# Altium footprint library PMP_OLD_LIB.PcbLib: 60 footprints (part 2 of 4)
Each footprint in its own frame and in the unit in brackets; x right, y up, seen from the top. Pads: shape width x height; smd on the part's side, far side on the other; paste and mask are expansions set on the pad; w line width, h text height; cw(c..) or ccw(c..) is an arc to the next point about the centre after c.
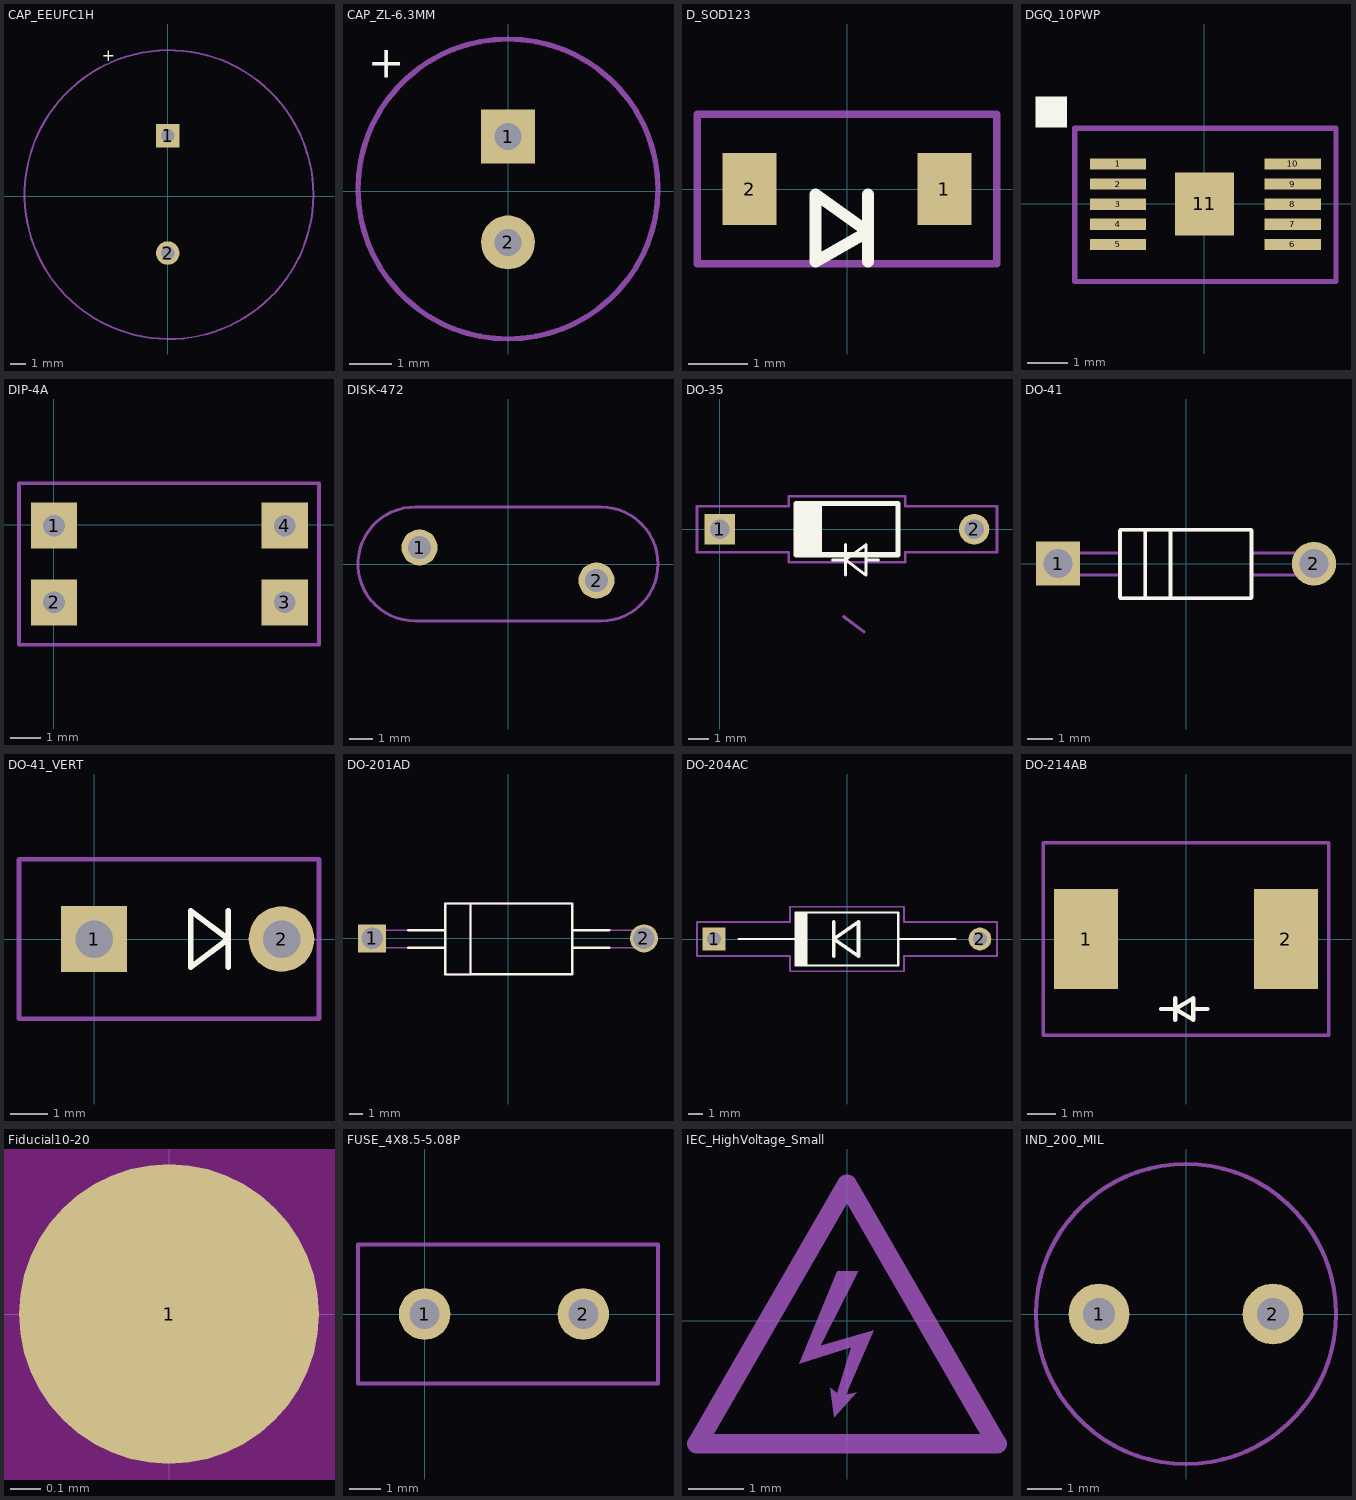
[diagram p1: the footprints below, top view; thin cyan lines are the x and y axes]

## CAP_EEUFC1H [mil]
pads (2):
  rect 60x60 hole 35: 1(0.1,155)
  round 60 hole 35: 2(0,-145)
Top Overlay:
  text "+" at -133.85,372.79 h30
Mechanical 5:
  circle w5: c3.4,4.6 r369.5
  text "+" at -145,380 h30
  text ".Designator" at -385,350 h60

## CAP_ZL-6.3MM [mil]
pads (2):
  rect 50x50 hole 25: 1(0,50.5)
  round 50 hole 25: 2(0,-47.5)
Top Overlay:
  text "+" at -130,105 h30
Mechanical 5:
  circle w5: c0,2 r139
  text "+" at -130,105 h30
  text ".Designator" at 135,-55 h60

## D_SOD123 [mil]
pads (2):
  rect 36x48 smd: 1(65,0) 2(-65,0)
Top Overlay:
  lines w8: 14,-48.5 14,-3.5 ; -21,-48.5 14,-28.5 -21,-3.5 -21,-48.5
Mechanical 5:
  lines w5: 14,-49.5 14,-4.5 ; -100,-50 100,-50 100,50 -100,50 -100,-50 ; -21,-49.5 14,-29.5 -21,-4.5 -21,-49.5
  text ".Designator" at -107,-110 h40

## DGQ_10PWP [mil]
pads (11):
  rect 55x11 smd: 1(-84.5,39) 2(-84.5,19.3) 3(-84.5,-0.4) 4(-84.5,-20.1) 5(-84.5,-39.8) 6(86.5,-39.8) 7(86.5,-20.1) 8(86.5,-0.4) 9(86.5,19.3) 10(86.5,39)
  rect 57.87x61.81 smd: 11(0,0)
Top Overlay:
  region: -165,75 -135,75 -135,105 -165,105
Mechanical 5:
  lines w5: -127,-76 128.9,-76 128.9,74 -127,74 -127,-76
  text "*" at -153.5,55.2 h60
  text ".Designator" at 27.5,-115.8 h60

## DIP-4A [mil]
pads (4):
  rect 60x60 hole 28: 1(0.5,-1) 2(0.5,-101) 3(300.5,-101) 4(300.5,-1)
Mechanical 5:
  lines w5: -45,-156 -45,54 345,54 345,-156 -45,-156
  text ".Designator" at -65,-90 h60

## DISK-472 [mil]
pads (2):
  round 60 hole 38: 1(-147.5,27.5) 2(147.5,-27.5)
Mechanical 5:
  lines w5: -154.17,95 ccw(c-155,0) -155,-95 155,-95 ccw(c155,0) 155,95 -154.1,95
  text ".Designator" at 295,-35 h60

## DO-35 [mil]
pads (2):
  rect 60x60 hole 38: 1(0,0)
  round 60 hole 38: 2(500,0)
Top Overlay:
  region: 150,-50 200,-50 200,50 150,50
  lines w6: 247,-60 287,-90 ; 247,-60 287,-30 ; 247,-60 287,-30 ; 247,-60 287,-90 ; 247,-60 222,-60 247,-60 ; 287,-90 287,-30 ; 287,-90 287,-30 ; 247,-90 247,-30 247,-90 ; 287,-60 312,-60 287,-60
  lines w10: 150,50 150,-50 350,-50 350,50 ; 150,51 350,51
Mechanical 5:
  lines w5: -45,-45 135,-45 135,-65 365,-65 365,-45 545,-45 545,45 365,45 365,65 135,65 135,45 -45,45 -45,-45
  lines w6: 243,-171.5 283,-201.5
  text ".Designator" at 198,93.5 h60

## DO-41 [mm] "diode"
height 3
pads (2):
  rect 1.75x1.75 hole 1.15: 1(-5.08,0)
  round 1.75 hole 1.15: 2(5.08,0)
Top Overlay:
  lines w0.152: -1.615,-1.371 -0.615,-1.371 ; -1.615,1.347 -0.615,1.347 ; -2.615,-1.322 ccw(c-2.565,-1.322) -2.565,-1.372 -1.615,-1.372 -1.615,-0.012 -1.615,1.348 -2.565,1.348 ccw(c-2.565,1.298) -2.615,1.298 -2.615,-0.012 -2.615,-1.322 ; -0.615,-1.372 -0.615,1.348 2.545,1.348 cw(c2.545,1.298) 2.595,1.298 2.595,-1.322 cw(c2.545,-1.322) 2.545,-1.372 -0.615,-1.372
Mechanical 5:
  lines w0.127: -2.615,-0.444 -4.09,-0.444 -5.09,-0.444 cw(c-5.09,-0.012) -5.522,-0.012 cw(c-5.09,-0.012) -5.09,0.42 -4.09,0.42 -2.615,0.42 ; -1.615,-1.371 -0.615,-1.371 ; -1.615,1.347 -0.615,1.347 ; 2.595,-0.444 4.07,-0.444 5.07,-0.444 ccw(c5.07,-0.012) 5.502,-0.012 ccw(c5.07,-0.012) 5.07,0.42 4.07,0.42 2.595,0.42 ; -2.615,-1.322 ccw(c-2.565,-1.322) -2.565,-1.372 -1.615,-1.372 -1.615,-0.012 -1.615,1.348 -2.565,1.348 ccw(c-2.565,1.298) -2.615,1.298 -2.615,-0.012 -2.615,-1.322 ; -0.615,-1.372 2.545,-1.372 ccw(c2.545,-1.322) 2.595,-1.322 2.595,1.298 ccw(c2.545,1.298) 2.545,1.348 -0.615,1.348 -0.615,-1.372
  text ".Designator" at -1.905,2.54 h1.52
3D body: height 2.72, standoff -2.6, extent -5.512,-1.36 5.512,1.36

## DO-41_VERT [mil]
pads (2):
  rect 70x70 hole 40: 1(0,0)
  round 70 hole 40: 2(200,0)
Top Overlay:
  lines w6: 103,-30 143,0 ; 103,-30 143,0 ; 103,-30 103,30 ; 103,-30 103,30 ; 103,30 143,0 ; 103,30 143,0 ; 143,-30 143,30 143,-30
Mechanical 5:
  lines w5: 103,-30 143,0 ; 103,-30 103,30 ; 103,-30 103,30 ; 103,-30 143,0 ; 103,30 143,0 ; 103,30 143,0 ; -80,-85 -80,85 240,85 240,-85 -80,-85 ; 143,-30 143,30 143,-30
  text ".Designator" at 25,110 h60

## DO-201AD [mm] "Vishay dimensions"
height 5.5
pads (2):
  rect 2.1x2.1 hole 1.6: 1(-10.16,0)
  round 2.1 hole 1.6: 2(10.16,0)
Top Overlay:
  lines w0.178: -7.47,-0.7 -4.7,-0.7 ; -7.47,0.62 -4.7,0.62 ; -2.8,-2.69 4.8,-2.69 4.8,2.61 -2.8,2.61 ; 4.8,-0.7 7.57,-0.7 ; 4.8,0.62 7.57,0.62 ; -2.8,2.61 -4.7,2.61 -4.7,-2.7 -2.8,-2.7 -2.8,2.61
Mechanical 5:
  lines w0.127: -4.7,-0.7 -7.47,-0.7 -10.11,-0.7 cw(c-10.11,-0.04) -10.11,0.62 -7.47,0.62 -4.7,0.62 ; -2.8,-2.69 4.8,-2.69 4.8,2.61 -2.8,2.61 ; 4.8,-0.7 7.57,-0.7 10.21,-0.7 ccw(c10.21,-0.04) 10.21,0.62 7.57,0.62 4.8,0.62 ; -2.8,2.61 -2.8,-2.7 -4.7,-2.7 -4.7,2.61 -2.8,2.61
  text ".Designator" at -0.864,3.81 h1.52
3D body: height 5.3, standoff -2.54, extent -10.819,-2.68 10.819,2.609

## DO-204AC [mil]
pads (2):
  rect 60x60 hole 37: 1(-350,0)
  round 60 hole 37: 2(350,0)
Top Overlay:
  region: -135,-70 -105,-70 -105,70 -135,70
  lines w6: -285,0 -135,0 ; 135,0 285,0 ; -135,-70 -135,70 135,70 135,-70 -135,-70
  lines w10: -35,-45 -35,45 ; -35,0 30,-45 30,45 -35,0
Mechanical 5:
  lines w5: -395,-45 -395,45 -150,45 -150,85 150,85 150,45 395,45 395,-45 150,-45 150,-85 -150,-85 -150,-45 -395,-45
  text ".Designator" at 370,-85 h60

## DO-214AB [mil]
pads (2):
  rect 90x140 smd: 1(-140,0) 2(140,0)
Top Overlay:
  lines w6: -15,-98 -35,-98 -15,-98 ; -15,-98 10,-113 ; -15,-98 10,-83 ; -15,-98 10,-113 ; -15,-98 10,-83 ; 10,-113 10,-83 ; 10,-113 10,-83 ; -15,-113 -15,-83 -15,-113 ; 10,-98 30,-98 10,-98
Mechanical 5:
  lines w5: -15,-98 -35,-98 -15,-98 ; -15,-98 10,-83 ; -15,-98 10,-113 ; -15,-98 10,-83 ; -15,-98 10,-113 ; 10,-113 10,-83 ; 10,-113 10,-83 ; -200,-135 -200,135 200,135 200,-135 -200,-135 ; -15,-113 -15,-83 -15,-113 ; 10,-98 30,-98 10,-98
  text ".Designator" at -55,-225 h60

## Fiducial10-20 [mm]
pads (1):
  round 1 smd paste+0 mask+0.5: 1(0,0)
Top Layer keep-out:
  circle w1.178: c0,0 r0.5

## FUSE_4X8.5-5.08P [mil]
pads (2):
  round 65 / inner rect 65x65 / far side rect 65x65 hole 38: 1(0,0) 2(200,0)
Mechanical 5:
  lines w5: -84.01,-87.5 -84.01,87.5 ; -83.86,-87.4 294.09,-87.4 ; -83.86,87.4 294.09,87.4 ; -47.4,87.5 257.48,87.4 ; 294.11,-87.5 294.11,87.5
  text ".Designator" at 120,-120 h60

## IEC_HighVoltage_Small [mil]
Mechanical 5:
  region: -7,35 8,35 -19,-18 19,-7 -1,-53 7,-51 -9,-69 -12,-48 -7,-52 3,-19 -34,-31
  lines w14: -107,-88 0,97.33 107,-88 -107,-88

## IND_200_MIL [mil]
pads (2):
  round 70 hole 37: 1(-100,0) 2(100,0)
Mechanical 5:
  circle w5: c0,0 r172.5
  text ".Designator" at -35,205 h40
